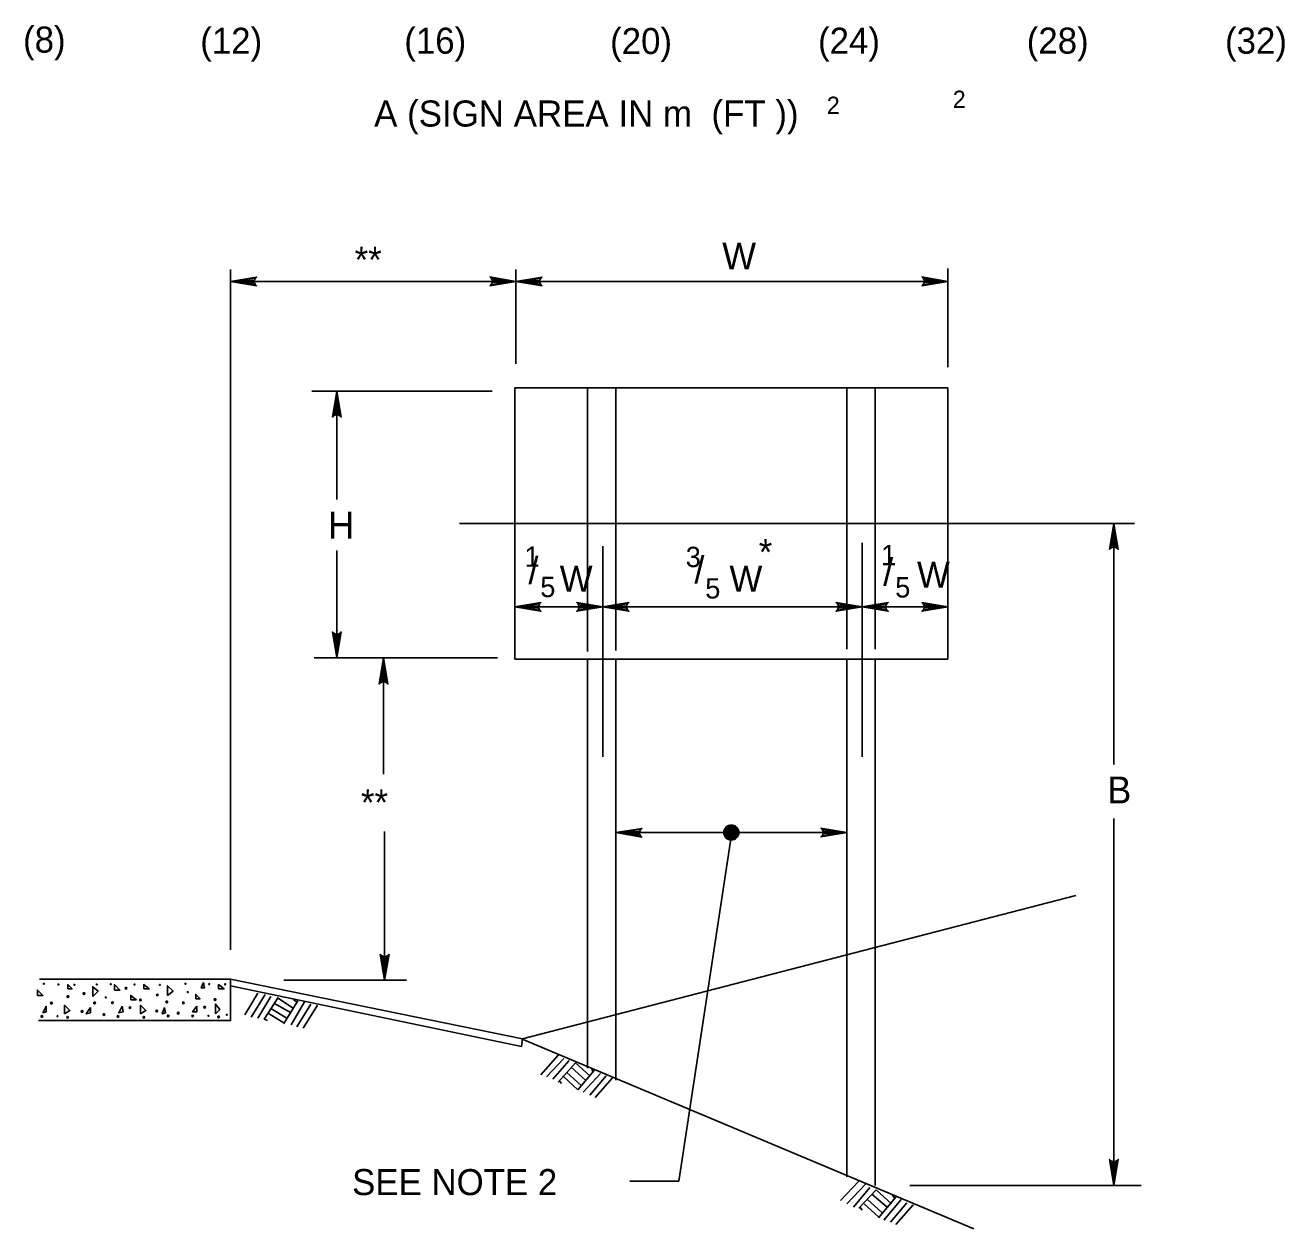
# Model space of a CAD drawing. Extents: x 644358 to 648627, y 294594 to 295782.
# Drawn here: x 645591.9 to 645737, y 295496.9 to 295635.5 of the extents above; entities that cross this region are included whole.
import ezdxf

# ---------------------------------------------------------------- set-up
doc = ezdxf.new("R2010")
doc.units = 0
for name, color, linetype in [('1', 7, 'Continuous'), ('2', 7, 'Continuous'), ('3', 7, 'Continuous'), ('4', 7, 'Continuous')]:
    doc.layers.add(name, color=color, linetype=linetype)

# ---------------------------------------------------------------- blocks, each defined once
blk = doc.blocks.new('RARROW')
at = {"layer": '3'}
blk.add_lwpolyline([(-2.2695, 0.285), (-2.184875, 0.12075), (0, 0), (-2.2695, 0.285), (-2.38575, 0.384625), (0, 0), (-2.183125, -0.108), (-2.262875, -0.2705), (0, 0), (-2.38575, -0.379125), (-2.262875, -0.2705)], dxfattribs=at)

msp = doc.modelspace()

# ---------------------------------------------------------------- linework, layer by layer
at = {"layer": '1'}
for p, q in [((645618.69, 295524.04), (645617.19, 295521.54)), ((645619.56, 295523.91), (645617.94, 295521.29)), ((645620.19, 295523.66), (645618.69, 295521.16)), ((645621.06, 295523.54), (645619.44, 295521.04)), ((645622.81, 295522.29), (645620.94, 295523.54)), ((645623.19, 295523.04), (645622.81, 295523.29)), ((645621.81, 295520.54), (645619.81, 295521.79)), ((645622.06, 295521.16), (645620.19, 295522.29)), ((645622.56, 295521.79), (645620.56, 295522.91)), ((645623.31, 295523.16), (645621.69, 295520.54)), ((645624.06, 295523.04), (645622.56, 295520.41)), ((645624.81, 295522.79), (645623.19, 295520.16)), ((645625.56, 295522.66), (645623.94, 295520.04)), ((645619.81, 295520.91), (645619.44, 295521.04)), ((645653.31, 295516.91), (645651.31, 295514.66)), ((645653.94, 295516.54), (645651.94, 295514.41)), ((645654.56, 295516.29), (645652.69, 295514.16)), ((645655.31, 295516.04), (645653.31, 295513.79)), ((645656.94, 295514.54), (645655.31, 295516.04)), ((645655.94, 295513.41), (645654.31, 295514.91)), ((645656.44, 295514.04), (645654.81, 295515.54)), ((645657.44, 295515.16), (645655.56, 295512.91)), ((645658.19, 295514.79), (645656.19, 295512.66)), ((645658.81, 295514.54), (645656.94, 295512.29)), ((645657.31, 295514.91), (645657.19, 295515.29)), ((645653.69, 295513.66), (645653.44, 295513.91)), ((645655.56, 295512.91), (645653.94, 295514.41)), ((645659.56, 295514.29), (645657.56, 295512.04)), ((645687.94, 295502.41), (645685.81, 295500.16)), ((645688.69, 295502.04), (645686.56, 295499.79)), ((645689.19, 295501.66), (645687.31, 295499.41)), ((645689.94, 295501.41), (645687.94, 295499.29)), ((645690.56, 295498.79), (645688.94, 295500.29)), ((645691.19, 295499.41), (645689.44, 295500.91)), ((645691.69, 295499.79), (645689.94, 295501.41)), ((645692.19, 295500.54), (645690.19, 295498.16)), ((645692.81, 295500.29), (645690.81, 295497.91)), ((645692.06, 295500.41), (645691.81, 295500.79)), ((645688.31, 295499.04), (645688.06, 295499.41)), ((645690.19, 295498.29), (645688.56, 295499.79)), ((645693.44, 295499.91), (645691.56, 295497.66)), ((645694.19, 295499.66), (645692.19, 295497.41))]:
    msp.add_line(p, q, dxfattribs=at)
for points in [[(645596.81, 295524.54), (645596.81, 295525.04), (645597.31, 295524.54)], [(645599.69, 295523.66), (645599.69, 295524.79), (645600.31, 295524.29)], [(645602.19, 295524.41), (645602.19, 295525.04), (645602.81, 295524.41)], [(645605.56, 295524.54), (645605.56, 295525.04), (645606.19, 295524.54)], [(645608.31, 295523.79), (645608.31, 295524.91), (645608.94, 295524.29)], [(645612.44, 295525.29), (645612.56, 295524.66), (645612.19, 295524.66)], [(645614.19, 295524.54), (645614.19, 295525.04), (645614.81, 295524.54)], [(645593.31, 295523.79), (645593.31, 295524.41), (645593.94, 295523.79)], [(645604.06, 295523.29), (645604.06, 295523.79), (645604.69, 295523.29)], [(645611.56, 295523.41), (645611.56, 295523.91), (645612.06, 295523.41)], [(645594.31, 295522.54), (645594.31, 295521.91), (645593.94, 295521.79)], [(645596.44, 295521.66), (645596.44, 295522.66), (645597.06, 295522.04)], [(645599.44, 295522.41), (645599.44, 295521.79), (645598.94, 295521.66)], [(645603.06, 295522.54), (645603.19, 295521.91), (645602.69, 295521.79)], [(645605.19, 295521.66), (645605.19, 295522.66), (645605.81, 295522.04)], [(645607.94, 295522.41), (645608.06, 295521.79), (645607.69, 295521.66)], [(645611.69, 295522.54), (645611.69, 295521.91), (645611.19, 295521.91)], [(645613.81, 295521.66), (645613.81, 295522.79), (645614.31, 295522.16)]]:
    msp.add_lwpolyline(points, close=True, dxfattribs=at)
for centre, radius in [((645594.04, 295525.14), 0.056), ((645595.73, 295525.05), 0.056), ((645597.57, 295525.02), 0.056), ((645600.15, 295525.05), 0.056), ((645601.77, 295525.08), 0.056), ((645603.52, 295524.62), 0.0979), ((645604.51, 295525.05), 0.056), ((645607.43, 295525.01), 0.056), ((645610.37, 295525.13), 0.056), ((645613.1, 295525.1), 0.056), ((645614.94, 295525.07), 0.056), ((645596.83, 295523.66), 0.0979), ((645598.67, 295524.01), 0.0979), ((645601.19, 295523.56), 0.056), ((645605.18, 295523.27), 0.0979), ((645607.13, 295523.84), 0.0979), ((645610.63, 295524.18), 0.056), ((645613.78, 295523.32), 0.0979), ((645594.93, 295522.91), 0.0979), ((645598.46, 295521.95), 0.0979), ((645599.9, 295522.93), 0.0979), ((645601.96, 295522.96), 0.0979), ((645603.98, 295522.38), 0.0979), ((645607.06, 295522), 0.0979), ((645608.22, 295523.05), 0.0979), ((645609.53, 295521.75), 0.0979), ((645610.13, 295522.94), 0.0979), ((645612.58, 295522.43), 0.0979), ((645593.83, 295521.37), 0.0979), ((645595.64, 295521.4), 0.056), ((645596.8, 295521.27), 0.0979), ((645600.97, 295521.59), 0.0979), ((645602.6, 295521.37), 0.0979), ((645605.58, 295521.27), 0.0979), ((645608.38, 295521.42), 0.0979), ((645611.2, 295521.42), 0.0979), ((645613.01, 295521.45), 0.056), ((645614.18, 295521.32), 0.0979), ((645615.13, 295521.57), 0.056)]:
    msp.add_circle(centre, radius, dxfattribs=at)
at = {"layer": '2'}
for p, q in [((645648.31, 295593.79), (645648.31, 295562.54)), ((645698.19, 295593.79), (645648.31, 295593.79)), ((645656.69, 295593.79), (645656.69, 295563.41)), ((645659.94, 295593.79), (645659.94, 295563.54)), ((645686.56, 295593.79), (645686.56, 295563.66)), ((645689.81, 295593.79), (645689.81, 295563.66)), ((645698.19, 295562.54), (645698.19, 295593.79)), ((645658.44, 295575.54), (645658.44, 295551.29)), ((645688.31, 295575.91), (645688.31, 295551.29)), ((645648.31, 295562.54), (645698.19, 295562.54)), ((645648.31, 295562.54), (645648.31, 295562.54)), ((645656.69, 295562.41), (645656.69, 295515.41)), ((645659.94, 295562.54), (645659.94, 295514.04)), ((645686.56, 295562.54), (645686.56, 295502.91)), ((645689.81, 295562.54), (645689.81, 295501.91)), ((645649.19, 295518.79), (645712.94, 295535.29)), ((645615.56, 295525.66), (645593.56, 295525.66)), ((645615.56, 295525.66), (645649.19, 295518.79)), ((645615.56, 295525.66), (645615.56, 295520.91)), ((645615.56, 295524.91), (645649.06, 295517.91)), ((645615.56, 295520.91), (645593.44, 295520.91)), ((645649.06, 295518.79), (645701.19, 295496.91)), ((645649.19, 295518.79), (645649.06, 295517.91))]:
    msp.add_line(p, q, dxfattribs=at)
at = {"layer": '4'}
for p, q in [((645615.56, 295607.41), (645615.56, 295529.04)), ((645648.44, 295607.41), (645648.44, 295596.54)), ((645698.19, 295607.54), (645698.19, 295596.16)), ((645648.44, 295606.04), (645615.56, 295606.04)), ((645698.06, 295606.04), (645648.44, 295606.04)), ((645645.69, 295593.41), (645624.93, 295593.41)), ((645627.81, 295593.41), (645627.81, 295580.91)), ((645641.94, 295578.16), (645719.69, 295578.16)), ((645717.31, 295578.16), (645717.31, 295550.41)), ((645627.81, 295575.04), (645627.81, 295562.66)), ((645648.44, 295568.54), (645648.31, 295568.54)), ((645658.31, 295568.54), (645648.44, 295568.54)), ((645688.31, 295568.54), (645658.31, 295568.54)), ((645698.06, 295568.54), (645688.31, 295568.54)), ((645698.19, 295568.54), (645698.06, 295568.54)), ((645646.31, 295562.66), (645625.18, 295562.66)), ((645633.19, 295562.66), (645633.19, 295549.29)), ((645717.31, 295544.16), (645717.31, 295501.91)), ((645633.31, 295542.66), (645633.31, 295525.54)), ((645686.56, 295542.54), (645659.94, 295542.54)), ((645673.31, 295542.54), (645667.19, 295502.41)), ((645635.81, 295525.54), (645621.69, 295525.54)), ((645667.19, 295502.41), (645661.56, 295502.41)), ((645720.44, 295501.91), (645693.81, 295501.91))]:
    msp.add_line(p, q, dxfattribs=at)
for radius in [0.867, 0.806, 0.744, 0.682, 0.621, 0.559, 0.498, 0.436, 0.374, 0.313, 0.251, 0.19, 0.128, 0.0665]:
    msp.add_circle((645673.24, 295542.55), radius, dxfattribs=at)

# ---------------------------------------------------------------- block references
at = {"layer": '2', "xscale": 1.2574347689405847, "yscale": 1.3092961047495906}
for p, rotation in [((645615.56, 295606.04), 180), ((645648.44, 295606.04), 180), ((645627.81, 295593.41), 89.99999999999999), ((645717.31, 295578.16), 89.99999999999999), ((645648.31, 295568.54), 180), ((645658.44, 295568.54), 180), ((645688.31, 295568.54), 180), ((645627.81, 295562.66), -90.00000000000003), ((645633.19, 295562.66), 89.99999999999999), ((645659.94, 295542.54), 180), ((645633.31, 295525.54), -90.00000000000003), ((645717.31, 295501.91), -90.00000000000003)]:
    msp.add_blockref('RARROW', p, dxfattribs=dict(at, rotation=rotation))
for p in [(645648.44, 295606.04), (645698.19, 295606.04), (645658.44, 295568.54), (645688.31, 295568.54), (645698.19, 295568.54), (645686.56, 295542.54)]:
    msp.add_blockref('RARROW', p, dxfattribs=at)

# ---------------------------------------------------------------- texts
at = {"layer": '4'}
for s, height, p in [('(8)', 3, (645591.66, 295632.39)), ('(12)', 3, (645612.07, 295632.25)), ('(16)', 3, (645635.57, 295632.26)), ('(20)', 3, (645659.28, 295632.22)), ('(24)', 3, (645683.23, 295632.26)), ('(28)', 3, (645707.27, 295632.27)), ('(32)', 3, (645730.11, 295632.26)), ('2', 2, (645698.75, 295626.01)), ('A (SIGN AREA IN m  (FT ))', 3.005, (645632.1, 295623.87)), ('2', 2, (645684.24, 295625.32)), ('W', 3.09, (645672.19, 295607.41)), ('**', 3, (645629.85, 295607.03)), ('H', 3.09, (645626.81, 295576.41)), ('1', 2.34, (645649.42, 295573.17)), ('3', 2.34, (645667.99, 295573.13)), ('*', 3, (645676.4, 295573.36)), ('1', 2.34, (645690.49, 295573.34)), ('/', 3.11, (645649.87, 295571.17)), ('/', 3.11, (645668.99, 295571.26)), ('/', 3.11, (645690.74, 295571.01)), ('W', 3, (645653.48, 295570.29)), ('W', 3, (645673.03, 295570.29)), ('W', 3, (645694.63, 295570.76)), ('5', 2.34, (645651.24, 295569.67)), ('5', 2.34, (645670.24, 295569.51)), ('5', 2.34, (645692.12, 295569.63)), ('B', 3.09, (645716.56, 295545.91)), ('**', 3, (645630.58, 295544.52)), ('SEE NOTE 2', 3, (645629.56, 295500.79))]:
    msp.add_text(s, height=height, dxfattribs=at).set_placement(p)

doc.saveas('drawing.dxf')
